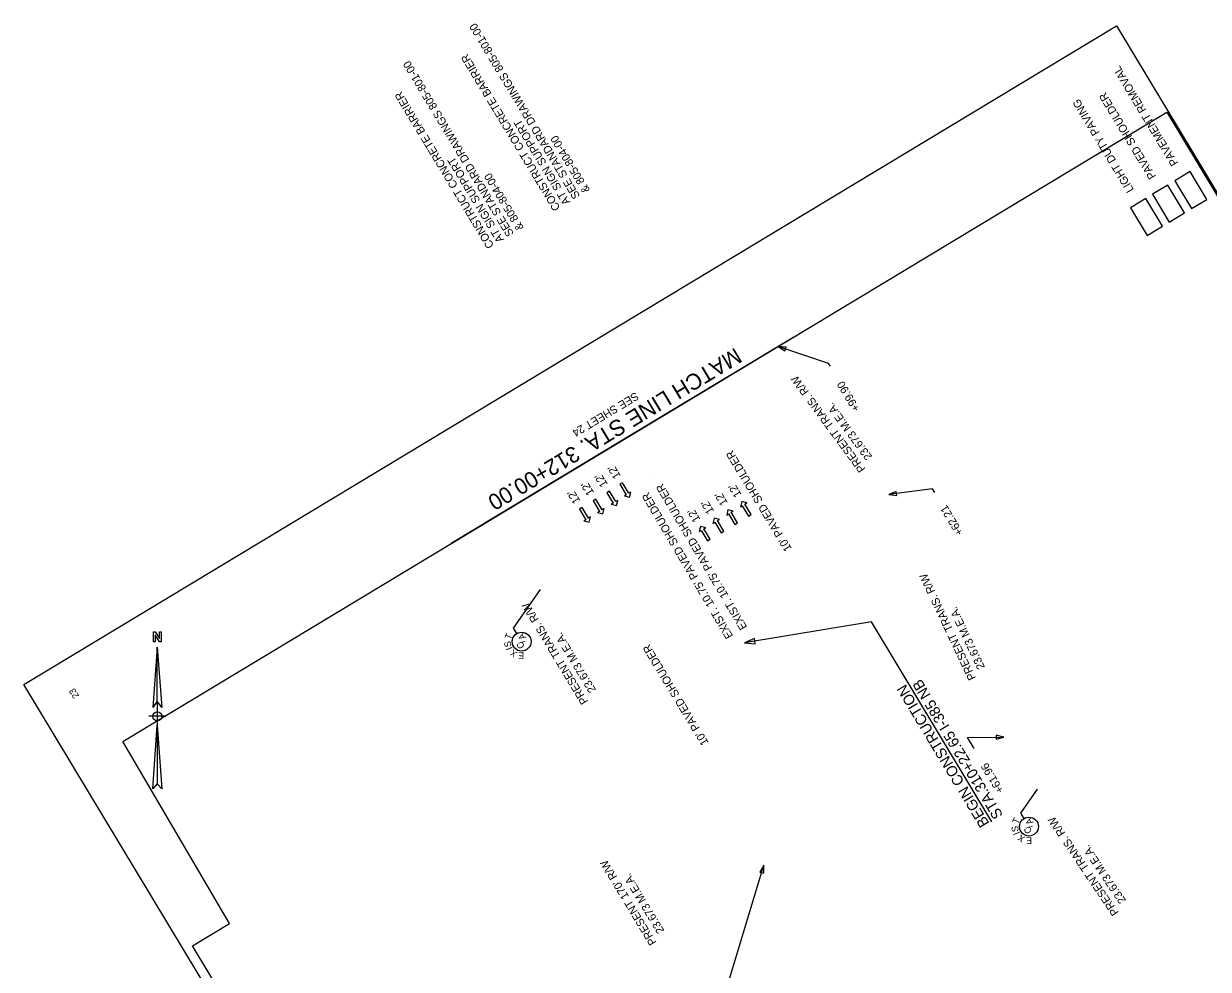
# Model space of a CAD drawing. Extents: x 1613170 to 1614989, y 1084261 to 1086549.
# Drawn here: x 1613269 to 1614158, y 1085483 to 1086191 of the extents above; entities that cross this region are included whole.
import ezdxf

# ---------------------------------------------------------------- set-up
doc = ezdxf.new("R2010")
doc.units = 0
for name, color, linetype in [('Level 11', 7, 'Continuous'), ('Level 13', 7, 'Continuous'), ('Level 17', 7, 'Continuous'), ('Level 18', 7, 'Continuous'), ('Level 22', 7, 'Continuous'), ('Level 26', 7, 'Continuous'), ('Level 4', 7, 'Continuous'), ('Level 7', 7, 'Continuous'), ('Level 8', 7, 'Continuous')]:
    doc.layers.add(name, color=color, linetype=linetype)

msp = doc.modelspace()

# ---------------------------------------------------------------- linework, layer by layer
at = {"layer": 'Level 11'}
for points in [[(1613874.15, 1085934.6), (1613872.89, 1085936.69), (1613835.13, 1085949.36)], [(1613952.49, 1085839.89), (1613950.8, 1085842.7), (1613918.06, 1085838.59)], [(1613982.03, 1085648.19), (1613977.09, 1085656.39), (1614004.19, 1085656.69)]]:
    msp.add_lwpolyline(points, dxfattribs=at)
for points in [[(1613841.12, 1085948.99), (1613835.13, 1085949.36), (1613840.13, 1085946.05)], [(1613923.62, 1085840.85), (1613918.06, 1085838.59), (1613924.01, 1085837.77)], [(1613998.41, 1085655.07), (1614004.19, 1085656.69), (1613998.38, 1085658.18)]]:
    msp.add_lwpolyline(points, close=True, dxfattribs=at)
at = {"layer": 'Level 13'}
for points in [[(1613708.65, 1085841.08), (1613706.6, 1085839.84), (1613711.33, 1085831.99), (1613709.94, 1085831.15), (1613713.82, 1085830.19), (1613714.78, 1085834.07), (1613713.39, 1085833.23)], [(1613718.45, 1085847.34), (1613716.39, 1085846.11), (1613721.13, 1085838.25), (1613719.73, 1085837.41), (1613723.61, 1085836.45), (1613724.58, 1085840.33), (1613723.18, 1085839.49)], [(1613698.38, 1085834.89), (1613696.32, 1085833.65), (1613701.05, 1085825.8), (1613699.66, 1085824.95), (1613703.54, 1085823.99), (1613704.5, 1085827.87), (1613703.11, 1085827.03)], [(1613812.84, 1085822.24), (1613814.89, 1085823.48), (1613810.16, 1085831.34), (1613811.55, 1085832.18), (1613807.67, 1085833.14), (1613806.71, 1085829.26), (1613808.1, 1085830.1)], [(1613688.1, 1085828.7), (1613686.04, 1085827.46), (1613690.78, 1085819.6), (1613689.38, 1085818.76), (1613693.26, 1085817.8), (1613694.23, 1085821.68), (1613692.83, 1085820.84)], [(1613802.56, 1085816.05), (1613804.62, 1085817.29), (1613799.88, 1085825.14), (1613801.28, 1085825.98), (1613797.39, 1085826.95), (1613796.43, 1085823.06), (1613797.83, 1085823.9)], [(1613782, 1085803.66), (1613784.06, 1085804.9), (1613779.33, 1085812.76), (1613780.72, 1085813.6), (1613776.84, 1085814.56), (1613775.88, 1085810.68), (1613777.27, 1085811.52)], [(1613792.28, 1085809.85), (1613794.34, 1085811.09), (1613789.6, 1085818.95), (1613791, 1085819.79), (1613787.12, 1085820.75), (1613786.15, 1085816.87), (1613787.55, 1085817.71)]]:
    msp.add_lwpolyline(points, close=True, dxfattribs=at)
at = {"layer": 'Level 17'}
msp.add_lwpolyline([(1614088.48, 1084350.83), (1613395.85, 1085500.14), (1613423.76, 1085516.94), (1613343.67, 1085653.32), (1614126.43, 1086125.05), (1614900.68, 1084840.3)], close=True, dxfattribs=at)
msp.add_lwpolyline([(1614088.48, 1084350.83), (1613395.85, 1085500.14), (1613423.76, 1085516.94), (1613343.67, 1085653.32), (1614126.43, 1086125.05), (1614900.68, 1084840.3)], close=True, dxfattribs=at)
msp.add_lwpolyline([(1614088.48, 1084350.83), (1613395.85, 1085500.14), (1613423.76, 1085516.94), (1613343.67, 1085653.32), (1614126.43, 1086125.05), (1614900.68, 1084840.3)], close=True, dxfattribs=at)
at = {"layer": 'Level 18'}
for p, q in [((1613369.57, 1085724.11), (1613366.15, 1085678.8)), ((1613369.57, 1085683.45), (1613366.15, 1085678.8)), ((1613369.57, 1085683.45), (1613369.57, 1085665.61)), ((1613376.09, 1085672.22), (1613363.12, 1085672.22)), ((1613369.57, 1085665.61), (1613372.99, 1085617.77)), ((1613372.99, 1085617.77), (1613369.57, 1085621.59))]:
    msp.add_line(p, q, dxfattribs=at)
msp.add_lwpolyline([(1613372.51, 1085727.94), (1613371.28, 1085727.94), (1613367.86, 1085733.4), (1613367.86, 1085732.58), (1613367.86, 1085727.94), (1613366.63, 1085727.94), (1613366.63, 1085735.52), (1613367.86, 1085735.52), (1613371.28, 1085730.47), (1613371.28, 1085730.88), (1613371.28, 1085735.52), (1613372.51, 1085735.52), (1613372.51, 1085727.94)], dxfattribs=at)
for points in [[(1613369.57, 1085724.11), (1613372.99, 1085678.8), (1613369.57, 1085683.45)], [(1613369.57, 1085665.61), (1613369.57, 1085621.59), (1613366.15, 1085617.77)]]:
    msp.add_lwpolyline(points, close=True, dxfattribs=at)
msp.add_circle((1613369.6, 1085672.22), 3.45, dxfattribs=at)
at = {"layer": 'Level 22'}
for p, q in [((1613636.7, 1085738.18), (1613656.88, 1085767.22)), ((1613639.06, 1085734.26), (1613636.7, 1085738.18)), ((1614017.04, 1085599.54), (1614029.5, 1085617.5)), ((1614019.4, 1085595.62), (1614017.04, 1085599.54))]:
    msp.add_line(p, q, dxfattribs=at)
for centre in [(1613642.72, 1085728.19), (1614023.06, 1085589.55)]:
    msp.add_circle(centre, 7.08, dxfattribs=at)
at = {"layer": 'Level 26'}
msp.add_lwpolyline([(1613796.26, 1085419.7), (1613786.55, 1085435.81), (1613824.37, 1085560.6)], dxfattribs=at)
msp.add_lwpolyline([(1613824.18, 1085554.6), (1613824.37, 1085560.6), (1613821.21, 1085555.51)], close=True, dxfattribs=at)
at = {"layer": 'Level 4'}
msp.add_lwpolyline([(1614134, 1084261.49), (1613269.39, 1085696.09), (1614088.61, 1086189.82), (1614953.22, 1084755.22)], close=True, dxfattribs=at)
at = {"layer": 'Level 7'}
msp.add_lwpolyline([(1613846.83, 1085956.53), (1613718.36, 1085879.11), (1613589.88, 1085801.68)], dxfattribs=at)
at = {"layer": 'Level 8'}
msp.add_line((1613741.05, 1085854.75), (1613741.05, 1085854.75), dxfattribs=at)
for points in [[(1614156.43, 1086059.69), (1614143.9, 1086080.48), (1614132.38, 1086073.53), (1614144.9, 1086052.75)], [(1614139.78, 1086049.66), (1614127.26, 1086070.45), (1614115.73, 1086063.5), (1614128.26, 1086042.72)], [(1614123.14, 1086039.63), (1614110.61, 1086060.42), (1614099.09, 1086053.47), (1614111.62, 1086032.69)], [(1613817.19, 1085730.52), (1613809.9, 1085727.21), (1613817.86, 1085726.43)]]:
    msp.add_lwpolyline(points, close=True, dxfattribs=at)
for points in [[(1614156.43, 1086059.69), (1614143.9, 1086080.48), (1614132.38, 1086073.53), (1614144.9, 1086052.75), (1614156.43, 1086059.69)], [(1614139.78, 1086049.66), (1614127.26, 1086070.45), (1614115.73, 1086063.5), (1614128.26, 1086042.72), (1614139.78, 1086049.66)], [(1614123.14, 1086039.63), (1614110.61, 1086060.42), (1614099.09, 1086053.47), (1614111.62, 1086032.69), (1614123.14, 1086039.63)], [(1613995.29, 1085593.01), (1613904.91, 1085742.96), (1613809.9, 1085727.21)]]:
    msp.add_lwpolyline(points, dxfattribs=at)

# ---------------------------------------------------------------- texts
at = {"layer": 'Level 11'}
for s, rotation, p in [('PRESENT TRANS. R/W ', 126.25082, (1613900.79, 1085857.74)), ('+99.90', 121.0768, (1613896.61, 1085902.92)), ('  23.673 M.E.A.', 126.25082, (1613908.45, 1085863.36)), ('+62.21', 121.0768, (1613974.03, 1085809.96)), ('PRESENT TRANS. R/W ', 115.28749, (1613983.49, 1085700.95)), ('PRESENT TRANS. R/W ', 121.0768, (1613692.81, 1085683.35)), ('  23.673 M.E.A.', 115.28749, (1613992.08, 1085705.01)), ('  23.673 M.E.A.', 121.0768, (1613700.95, 1085688.26)), ('+61.96', 121.0768, (1614004.5, 1085616.73)), ('PRESENT TRANS. R/W ', 123.93831, (1614090.7, 1085525.22)), ('  23.673 M.E.A.', 123.93831, (1614098.58, 1085530.52)), ("PRESENT 170' R/W ", 121.0768, (1613744.09, 1085502.79)), ('  23.673 M.E.A.', 121.0768, (1613752.22, 1085507.7))]:
    msp.add_text(s, height=6, rotation=rotation, dxfattribs=at).set_placement(p)
at = {"layer": 'Level 22'}
for s, rotation, p in [('T', 66.91748, (1613634.4, 1085729.3)), ('A', 121.07355, (1613646.21, 1085731.39)), ('S', 100.4046, (1613635.17, 1085724.52)), ('C', 121.07355, (1613645.3, 1085724.66)), ('/', 121.07355, (1613645.58, 1085728.28)), ('I', 112.12509, (1613636.07, 1085723.07)), ('X', 146.17032, (1613640.08, 1085720.23)), ('E', 177.98309, (1613644.68, 1085720.03)), ('T', 64.12688, (1614014.76, 1085590.96)), ('A', 121.07355, (1614026.56, 1085592.76)), ('S', 99.28836, (1614015.47, 1085585.92)), ('I', 111.00885, (1614016.37, 1085584.45)), ('X', 146.17032, (1614020.53, 1085581.53)), ('C', 121.07355, (1614025.64, 1085586.03)), ('/', 121.07355, (1614025.92, 1085589.65)), ('E', 179.65744, (1614025.38, 1085581.46))]:
    msp.add_text(s, height=5, rotation=rotation, dxfattribs=at).set_placement(p)
at = {"layer": 'Level 7'}
for s, height, p in [('MATCH LINE STA. 312+00.00', 12, (1613802.86, 1085948.94)), ('SEE SHEET 24', 6, (1613728.11, 1085915.5))]:
    msp.add_text(s, height=height, rotation=211.12807, dxfattribs=at).set_placement(p)
at = {"layer": 'Level 8'}
for s, height, rotation, p in [('SEE STANDARD DRAWINGS 805-801-00', 6, 121.0768, (1613686.74, 1086062.21)), ('CONSTRUCT CONCRETE BARRIER ', 6, 121.0768, (1613671.93, 1086053.29)), ('SEE STANDARD DRAWINGS 805-801-00', 6, 121.0768, (1613637.06, 1086034.02)), ('PAVEMENT REMOVAL', 6, 121.0768, (1614135.21, 1086087.01)), ('CONSTRUCT CONCRETE BARRIER ', 6, 121.0768, (1613622.25, 1086025.1)), ('LIGHT DUTY PAVING', 6, 121.0768, (1614101.92, 1086066.95)), ('PAVED SHOULDER', 6, 121.0768, (1614118.56, 1086076.98)), ('AT SIGN SUPPORT', 6, 121.0768, (1613679.33, 1086057.75)), ('& 805-804-00', 6, 121.0768, (1613694.14, 1086066.67)), ('AT SIGN SUPPORT', 6, 121.0768, (1613629.65, 1086029.56)), ('& 805-804-00', 6, 121.0768, (1613644.46, 1086038.49)), ("10' PAVED SHOULDER", 6, 121.07517, (1613845.43, 1085797.94)), ("12'", 6, 121.07355, (1613717.3, 1085852.31)), ("12'", 6, 121.07355, (1613707.5, 1085846.05)), ("12'", 6, 121.07355, (1613686.95, 1085833.67)), ("12'", 6, 121.07355, (1613697.23, 1085839.86)), ("EXIST. 10.75' PAVED SHOULDER", 6, 120.51747, (1613801.38, 1085732.49)), ("EXIST. 10.75' PAVED SHOULDER", 6, 120.51747, (1613811.97, 1085739.15)), ("12'", 6, 121.07355, (1613807.77, 1085838.4)), ("12'", 6, 121.07355, (1613787.22, 1085826.02)), ("12'", 6, 121.07355, (1613797.49, 1085832.21)), ("12'", 6, 121.07355, (1613776.94, 1085819.82)), ("10' PAVED SHOULDER", 6, 121.07517, (1613783.05, 1085652.52)), ('STA.310+22.65 I-385 NB', 8, 121.07843, (1614003.86, 1085598.17)), ('23', 5, 121.0768, (1613311.14, 1085687.36)), ('BEGIN CONSTRUCTION', 8, 121.07843, (1613993.58, 1085591.98))]:
    msp.add_text(s, height=height, rotation=rotation, dxfattribs=at).set_placement(p)

doc.saveas('drawing.dxf')
